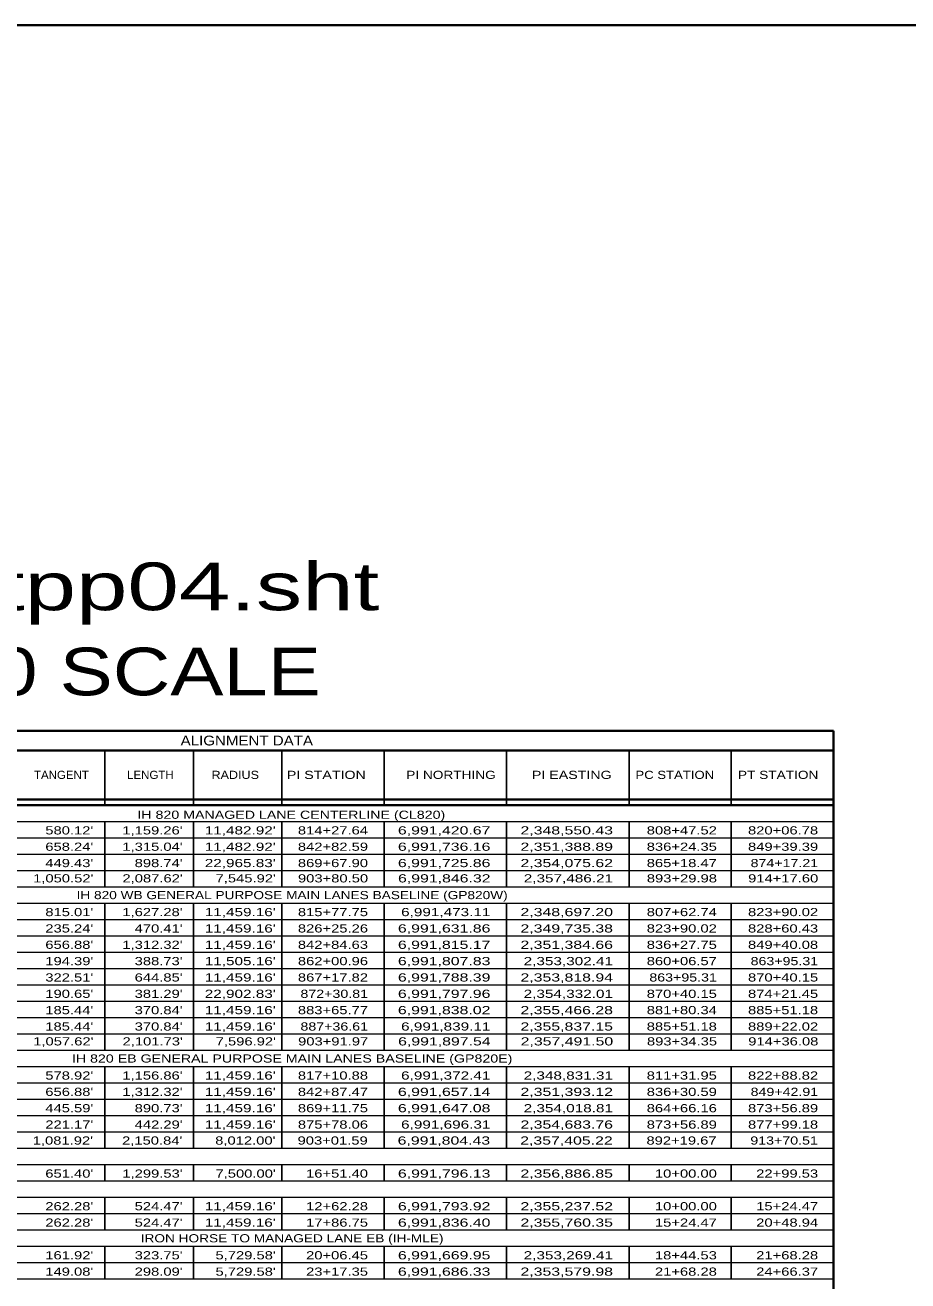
# Model space of a CAD drawing. Extents: x 1953053 to 1967065, y 7363860 to 7371201.
# Drawn here: x 1960493 to 1961790, y 7369357 to 7371201 of the extents above; entities that cross this region are included whole.
import ezdxf
from ezdxf.enums import TextEntityAlignment as Align

# ---------------------------------------------------------------- set-up
doc = ezdxf.new("R2010")
doc.units = 0
doc.header["$LTSCALE"] = 4.8
doc.layers.add('10', color=7, linetype='Continuous')
doc.layers.add('12', color=7, linetype='Continuous', lineweight=25)
doc.layers.add('62', color=7, linetype='Continuous', lineweight=35)

msp = doc.modelspace()

# ---------------------------------------------------------------- linework, layer by layer
at = {"layer": '12', "lineweight": 35}
for p, q in [((1961680.213, 7370164.879), (1959956.881, 7370164.879)), ((1961680.213, 7368159.747), (1961680.213, 7370164.879)), ((1959956.881, 7370136.079), (1961680.213, 7370136.079)), ((1961680.213, 7368111.747), (1961680.213, 7370116.879)), ((1959956.881, 7370064.079), (1961680.213, 7370064.079)), ((1959956.881, 7370055.746), (1961680.213, 7370055.746))]:
    msp.add_line(p, q, dxfattribs=at)
at = {"layer": '12'}
for p, q in [((1960610.213, 7370136.079), (1960610.213, 7370055.746)), ((1960740.213, 7370136.079), (1960740.213, 7370055.746)), ((1960870.213, 7370136.079), (1960870.213, 7370055.746)), ((1961020.213, 7370136.079), (1961020.213, 7370055.746)), ((1961200.213, 7370136.079), (1961200.213, 7370055.746)), ((1961380.213, 7370136.079), (1961380.213, 7370055.746)), ((1961530.213, 7370136.079), (1961530.213, 7370055.746)), ((1960610.213, 7370031.746), (1960610.213, 7369935.746)), ((1960740.213, 7370031.746), (1960740.213, 7369935.746)), ((1960870.213, 7370031.746), (1960870.213, 7369935.746)), ((1961020.213, 7370031.746), (1961020.213, 7369935.746)), ((1961200.213, 7370031.746), (1961200.213, 7369935.746)), ((1961380.213, 7370031.746), (1961380.213, 7369935.746)), ((1961530.213, 7370031.746), (1961530.213, 7369935.746)), ((1960610.213, 7369911.746), (1960610.213, 7369695.746)), ((1960740.213, 7369911.746), (1960740.213, 7369695.746)), ((1960870.213, 7369911.746), (1960870.213, 7369695.746)), ((1961020.213, 7369911.746), (1961020.213, 7369695.746)), ((1961200.213, 7369911.746), (1961200.213, 7369695.746)), ((1961380.213, 7369911.746), (1961380.213, 7369695.746)), ((1961530.213, 7369911.746), (1961530.213, 7369695.746)), ((1960610.213, 7369671.746), (1960610.213, 7369551.746)), ((1960740.213, 7369671.746), (1960740.213, 7369551.746)), ((1960870.213, 7369671.746), (1960870.213, 7369551.746)), ((1961020.213, 7369671.746), (1961020.213, 7369551.746)), ((1961200.213, 7369671.746), (1961200.213, 7369551.746)), ((1961380.213, 7369671.746), (1961380.213, 7369551.746)), ((1961530.213, 7369671.746), (1961530.213, 7369551.746)), ((1960610.213, 7369527.746), (1960610.213, 7369503.746)), ((1960740.213, 7369527.746), (1960740.213, 7369503.746)), ((1960870.213, 7369527.746), (1960870.213, 7369503.746)), ((1961020.213, 7369527.746), (1961020.213, 7369503.746)), ((1961200.213, 7369527.746), (1961200.213, 7369503.746)), ((1961380.213, 7369527.746), (1961380.213, 7369503.746)), ((1961530.213, 7369527.746), (1961530.213, 7369503.746)), ((1960610.213, 7369479.746), (1960610.213, 7369431.746)), ((1960740.213, 7369479.746), (1960740.213, 7369431.746)), ((1960870.213, 7369479.746), (1960870.213, 7369431.746)), ((1961020.213, 7369479.746), (1961020.213, 7369431.746)), ((1961200.213, 7369479.746), (1961200.213, 7369431.746)), ((1961380.213, 7369479.746), (1961380.213, 7369431.746)), ((1961530.213, 7369479.746), (1961530.213, 7369431.746)), ((1960610.213, 7369407.746), (1960610.213, 7369359.746)), ((1960740.213, 7369407.746), (1960740.213, 7369359.746)), ((1960870.213, 7369407.746), (1960870.213, 7369359.746)), ((1961020.213, 7369407.746), (1961020.213, 7369359.746)), ((1961200.213, 7369407.746), (1961200.213, 7369359.746)), ((1961380.213, 7369407.746), (1961380.213, 7369359.746)), ((1961530.213, 7369407.746), (1961530.213, 7369359.746))]:
    msp.add_line(p, q, dxfattribs=at)
at = {"layer": '12', "lineweight": 13}
for p, q in [((1959956.881, 7370007.746), (1961680.213, 7370007.746)), ((1959956.881, 7369983.746), (1961680.213, 7369983.746)), ((1959956.881, 7369959.746), (1961680.213, 7369959.746)), ((1959956.881, 7369935.746), (1961680.213, 7369935.746)), ((1959956.881, 7369911.746), (1961680.213, 7369911.746)), ((1959956.881, 7369887.746), (1961680.213, 7369887.746)), ((1959956.881, 7369863.746), (1961680.213, 7369863.746)), ((1959956.881, 7369839.746), (1961680.213, 7369839.746)), ((1959956.881, 7369815.746), (1961680.213, 7369815.746)), ((1959956.881, 7369791.746), (1961680.213, 7369791.746)), ((1959956.881, 7369767.746), (1961680.213, 7369767.746)), ((1959956.881, 7369743.746), (1961680.213, 7369743.746)), ((1959956.881, 7369719.746), (1961680.213, 7369719.746)), ((1959956.881, 7369695.746), (1961680.213, 7369695.746)), ((1959956.881, 7369647.746), (1961680.213, 7369647.746)), ((1959956.881, 7369623.746), (1961680.213, 7369623.746)), ((1959956.881, 7369599.746), (1961680.213, 7369599.746)), ((1959956.881, 7369575.746), (1961680.213, 7369575.746)), ((1959956.881, 7369551.746), (1961680.213, 7369551.746)), ((1959956.881, 7369527.746), (1961680.213, 7369527.746)), ((1959956.881, 7369503.746), (1961680.213, 7369503.746)), ((1959956.881, 7369479.746), (1961680.213, 7369479.746)), ((1959956.881, 7369455.746), (1961680.213, 7369455.746)), ((1959956.881, 7369431.746), (1961680.213, 7369431.746)), ((1959956.881, 7369407.746), (1961680.213, 7369407.746)), ((1959956.881, 7369383.746), (1961680.213, 7369383.746)), ((1959956.881, 7369359.746), (1961680.213, 7369359.746))]:
    msp.add_line(p, q, dxfattribs=at)
for points in [[(1959956.881, 7370031.746), (1960867.445, 7370031.746), (1961680.213, 7370031.746)], [(1959956.881, 7369671.746), (1961378.496, 7369671.746), (1961680.213, 7369671.746)]]:
    msp.add_lwpolyline(points, dxfattribs=at)
at = {"layer": '62'}
msp.add_lwpolyline([(1953052.784, 7371201.108), (1967065.314, 7371201.108), (1967065.314, 7363859.877), (1953052.784, 7363859.877)], close=True, dxfattribs=at)

# ---------------------------------------------------------------- texts
at = {"layer": '10'}
for s, width, p in [('IH 820 MANAGED LANE CENTERLINE (CL820)', 1.3, (1960884.005, 7370035.509)), ('IH 820 WB GENERAL PURPOSE MAIN LANES BASELINE (GP820W)', 1.25, (1960885.214, 7369917.54)), ('IH 820 EB GENERAL PURPOSE MAIN LANES BASELINE (GP820E)', 1.3, (1960885.214, 7369677.54)), ('IRON HORSE TO MANAGED LANE EB (IH-MLE)', 1.25, (1960885.213, 7369413.54))]:
    msp.add_text(s, height=12, dxfattribs=dict(at, width=width)).set_placement(p, align=Align.CENTER)
for s, width, p in [("580.12'", 1.35, (1960593.14, 7370012.573)), ("1,159.26'", 1.35, (1960724.337, 7370012.573)), ("11,482.92'", 1.4, (1960861.106, 7370012.573)), ('814+27.64', 1.35, (1960996.65, 7370012.573)), ('6,991,420.67', 1.45, (1961176.415, 7370012.573)), ('2,348,550.43', 1.45, (1961356.415, 7370012.573)), ('808+47.52', 1.35, (1961508.993, 7370012.573)), ('820+06.78', 1.35, (1961657.725, 7370012.573)), ("658.24'", 1.35, (1960593.14, 7369988.573)), ("1,315.04'", 1.35, (1960724.337, 7369988.573)), ("11,482.92'", 1.4, (1960861.106, 7369988.573)), ('842+82.59', 1.35, (1960996.65, 7369988.573)), ('6,991,736.16', 1.45, (1961176.415, 7369988.573)), ('2,351,388.89', 1.45, (1961356.415, 7369988.573)), ('836+24.35', 1.35, (1961508.993, 7369988.573)), ('849+39.39', 1.35, (1961657.725, 7369988.573)), ("449.43'", 1.35, (1960593.14, 7369964.573)), ("898.74'", 1.35, (1960724.337, 7369964.573)), ("22,965.83'", 1.4, (1960861.106, 7369964.573)), ('869+67.90', 1.35, (1960996.65, 7369964.573)), ('6,991,725.86', 1.45, (1961176.415, 7369964.573)), ('2,354,075.62', 1.45, (1961356.415, 7369964.573)), ('865+18.47', 1.35, (1961508.993, 7369964.573)), ('874+17.21', 1.3, (1961657.725, 7369964.573)), ("1,050.52'", 1.35, (1960593.294, 7369942.126)), ("2,087.62'", 1.35, (1960724.491, 7369942.126)), ("7,545.92'", 1.35, (1960861.26, 7369942.126)), ('903+80.50', 1.35, (1960996.804, 7369942.126)), ('6,991,846.32', 1.45, (1961176.569, 7369942.126)), ('2,357,486.21', 1.4, (1961356.569, 7369942.126)), ('893+29.98', 1.35, (1961509.147, 7369942.126)), ('914+17.60', 1.35, (1961657.879, 7369942.126)), ("815.01'", 1.35, (1960593.14, 7369892.573)), ("1,627.28'", 1.35, (1960724.337, 7369892.573)), ("11,459.16'", 1.4, (1960861.106, 7369892.573)), ('815+77.75', 1.35, (1960996.65, 7369892.573)), ('6,991,473.11', 1.4, (1961176.415, 7369892.573)), ('2,348,697.20', 1.45, (1961356.415, 7369892.573)), ('807+62.74', 1.35, (1961508.993, 7369892.573)), ('823+90.02', 1.35, (1961657.725, 7369892.573)), ("235.24'", 1.35, (1960593.14, 7369868.573)), ("470.41'", 1.35, (1960724.337, 7369868.573)), ("11,459.16'", 1.4, (1960861.106, 7369868.573)), ('826+25.26', 1.35, (1960996.65, 7369868.573)), ('6,991,631.86', 1.45, (1961176.415, 7369868.573)), ('2,349,735.38', 1.45, (1961356.415, 7369868.573)), ('823+90.02', 1.35, (1961508.993, 7369868.573)), ('828+60.43', 1.35, (1961657.725, 7369868.573)), ("656.88'", 1.35, (1960593.14, 7369844.573)), ("1,312.32'", 1.35, (1960724.337, 7369844.573)), ("11,459.16'", 1.4, (1960861.106, 7369844.573)), ('842+84.63', 1.35, (1960996.65, 7369844.573)), ('6,991,815.17', 1.45, (1961176.415, 7369844.573)), ('2,351,384.66', 1.45, (1961356.415, 7369844.573)), ('836+27.75', 1.35, (1961508.993, 7369844.573)), ('849+40.08', 1.35, (1961657.725, 7369844.573)), ("194.39'", 1.35, (1960593.14, 7369820.573)), ("388.73'", 1.35, (1960724.337, 7369820.573)), ("11,505.16'", 1.4, (1960861.106, 7369820.573)), ('862+00.96', 1.35, (1960996.65, 7369820.573)), ('6,991,807.83', 1.45, (1961176.415, 7369820.573)), ('2,353,302.41', 1.4, (1961356.415, 7369820.573)), ('860+06.57', 1.35, (1961508.993, 7369820.573)), ('863+95.31', 1.3, (1961657.725, 7369820.573)), ("322.51'", 1.35, (1960593.14, 7369796.573)), ("644.85'", 1.35, (1960724.337, 7369796.573)), ("11,459.16'", 1.4, (1960861.106, 7369796.573)), ('867+17.82', 1.35, (1960996.65, 7369796.573)), ('6,991,788.39', 1.45, (1961176.415, 7369796.573)), ('2,353,818.94', 1.45, (1961356.415, 7369796.573)), ('863+95.31', 1.3, (1961508.993, 7369796.573)), ('870+40.15', 1.35, (1961657.725, 7369796.573)), ("190.65'", 1.35, (1960593.14, 7369772.573)), ("381.29'", 1.35, (1960724.337, 7369772.573)), ("22,902.83'", 1.4, (1960861.106, 7369772.573)), ('872+30.81', 1.3, (1960996.65, 7369772.573)), ('6,991,797.96', 1.45, (1961176.415, 7369772.573)), ('2,354,332.01', 1.4, (1961356.415, 7369772.573)), ('870+40.15', 1.35, (1961508.993, 7369772.573)), ('874+21.45', 1.35, (1961657.725, 7369772.573)), ("185.44'", 1.35, (1960593.14, 7369748.573)), ("370.84'", 1.35, (1960724.337, 7369748.573)), ("11,459.16'", 1.4, (1960861.106, 7369748.573)), ('883+65.77', 1.35, (1960996.65, 7369748.573)), ('6,991,838.02', 1.45, (1961176.415, 7369748.573)), ('2,355,466.28', 1.45, (1961356.415, 7369748.573)), ('881+80.34', 1.35, (1961508.993, 7369748.573)), ('885+51.18', 1.35, (1961657.725, 7369748.573)), ("185.44'", 1.35, (1960593.14, 7369724.573)), ("370.84'", 1.35, (1960724.337, 7369724.573)), ("11,459.16'", 1.4, (1960861.106, 7369724.573)), ('887+36.61', 1.3, (1960996.65, 7369724.573)), ('6,991,839.11', 1.4, (1961176.415, 7369724.573)), ('2,355,837.15', 1.45, (1961356.415, 7369724.573)), ('885+51.18', 1.35, (1961508.993, 7369724.573)), ('889+22.02', 1.35, (1961657.725, 7369724.573)), ("1,057.62'", 1.35, (1960593.439, 7369702.722)), ("2,101.73'", 1.35, (1960724.636, 7369702.722)), ("7,596.92'", 1.35, (1960861.405, 7369702.722)), ('903+91.97', 1.35, (1960996.949, 7369702.722)), ('6,991,897.54', 1.45, (1961176.714, 7369702.722)), ('2,357,491.50', 1.45, (1961356.714, 7369702.722)), ('893+34.35', 1.35, (1961509.292, 7369702.722)), ('914+36.08', 1.35, (1961658.024, 7369702.722)), ("578.92'", 1.35, (1960593.14, 7369652.573)), ("1,156.86'", 1.35, (1960724.337, 7369652.573)), ("11,459.16'", 1.4, (1960861.106, 7369652.573)), ('817+10.88', 1.35, (1960996.65, 7369652.573)), ('6,991,372.41', 1.4, (1961176.415, 7369652.573)), ('2,348,831.31', 1.4, (1961356.415, 7369652.573)), ('811+31.95', 1.35, (1961508.993, 7369652.573)), ('822+88.82', 1.35, (1961657.725, 7369652.573)), ("656.88'", 1.35, (1960593.14, 7369628.573)), ("1,312.32'", 1.35, (1960724.337, 7369628.573)), ("11,459.16'", 1.4, (1960861.106, 7369628.573)), ('842+87.47', 1.35, (1960996.65, 7369628.573)), ('6,991,657.14', 1.45, (1961176.415, 7369628.573)), ('2,351,393.12', 1.45, (1961356.415, 7369628.573)), ('836+30.59', 1.35, (1961508.993, 7369628.573)), ('849+42.91', 1.3, (1961657.725, 7369628.573)), ("445.59'", 1.35, (1960593.14, 7369604.573)), ("890.73'", 1.35, (1960724.337, 7369604.573)), ("11,459.16'", 1.4, (1960861.106, 7369604.573)), ('869+11.75', 1.35, (1960996.65, 7369604.573)), ('6,991,647.08', 1.45, (1961176.415, 7369604.573)), ('2,354,018.81', 1.4, (1961356.415, 7369604.573)), ('864+66.16', 1.35, (1961508.993, 7369604.573)), ('873+56.89', 1.35, (1961657.725, 7369604.573)), ("221.17'", 1.35, (1960593.14, 7369580.573)), ("442.29'", 1.35, (1960724.337, 7369580.573)), ("11,459.16'", 1.4, (1960861.106, 7369580.573)), ('875+78.06', 1.35, (1960996.65, 7369580.573)), ('6,991,696.31', 1.4, (1961176.415, 7369580.573)), ('2,354,683.76', 1.45, (1961356.415, 7369580.573)), ('873+56.89', 1.35, (1961508.993, 7369580.573)), ('877+99.18', 1.35, (1961657.725, 7369580.573)), ("1,081.92'", 1.35, (1960592.726, 7369557.11)), ("2,150.84'", 1.35, (1960723.923, 7369557.11)), ("8,012.00'", 1.35, (1960860.692, 7369557.11)), ('903+01.59', 1.35, (1960996.236, 7369557.11)), ('6,991,804.43', 1.45, (1961176.001, 7369557.11)), ('2,357,405.22', 1.45, (1961356.001, 7369557.11)), ('892+19.67', 1.35, (1961508.579, 7369557.11)), ('913+70.51', 1.3, (1961657.311, 7369557.11)), ("651.40'", 1.35, (1960593.14, 7369508.573)), ("1,299.53'", 1.35, (1960724.337, 7369508.573)), ("7,500.00'", 1.35, (1960861.106, 7369508.573)), ('16+51.40', 1.35, (1960996.65, 7369508.573)), ('6,991,796.13', 1.45, (1961176.415, 7369508.573)), ('2,356,886.85', 1.45, (1961356.415, 7369508.573)), ('10+00.00', 1.35, (1961508.993, 7369508.573)), ('22+99.53', 1.35, (1961657.725, 7369508.573)), ("262.28'", 1.35, (1960593.14, 7369460.573)), ("524.47'", 1.35, (1960724.337, 7369460.573)), ("11,459.16'", 1.4, (1960861.106, 7369460.573)), ('12+62.28', 1.35, (1960996.65, 7369460.573)), ('6,991,793.92', 1.45, (1961176.415, 7369460.573)), ('2,355,237.52', 1.45, (1961356.415, 7369460.573)), ('10+00.00', 1.35, (1961508.993, 7369460.573)), ('15+24.47', 1.35, (1961657.725, 7369460.573)), ("262.28'", 1.35, (1960593.14, 7369436.573)), ("524.47'", 1.35, (1960724.337, 7369436.573)), ("11,459.16'", 1.4, (1960861.106, 7369436.573)), ('17+86.75', 1.35, (1960996.65, 7369436.573)), ('6,991,836.40', 1.45, (1961176.415, 7369436.573)), ('2,355,760.35', 1.45, (1961356.415, 7369436.573)), ('15+24.47', 1.35, (1961508.993, 7369436.573)), ('20+48.94', 1.35, (1961657.725, 7369436.573)), ("161.92'", 1.35, (1960593.14, 7369388.573)), ("323.75'", 1.35, (1960724.337, 7369388.573)), ("5,729.58'", 1.35, (1960861.106, 7369388.573)), ('20+06.45', 1.35, (1960996.65, 7369388.573)), ('6,991,669.95', 1.45, (1961176.415, 7369388.573)), ('2,353,269.41', 1.4, (1961356.415, 7369388.573)), ('18+44.53', 1.35, (1961508.993, 7369388.573)), ('21+68.28', 1.35, (1961657.725, 7369388.573)), ("149.08'", 1.35, (1960593.14, 7369364.573)), ("298.09'", 1.35, (1960724.337, 7369364.573)), ("5,729.58'", 1.35, (1960861.106, 7369364.573)), ('23+17.35', 1.35, (1960996.65, 7369364.573)), ('6,991,686.33', 1.45, (1961176.415, 7369364.573)), ('2,353,579.98', 1.45, (1961356.415, 7369364.573)), ('21+68.28', 1.35, (1961508.993, 7369364.573)), ('24+66.37', 1.35, (1961657.725, 7369364.573))]:
    msp.add_text(s, height=12, dxfattribs=dict(at, width=width)).set_placement(p, align=Align.RIGHT)
at = {"layer": '12'}
for s, height, width, p in [('ALIGNMENT DATA', 14.4, 1.15, (1960818.654, 7370143.278)), ('TANGENT', 12, 1.05, (1960546.401, 7370094.078)), ('LENGTH', 12, 1.05, (1960677.036, 7370094.078)), ('RADIUS', 12, 1.15, (1960801.646, 7370094.078)), ('PI STATION', 12, 1.3, (1960935.45, 7370094.078)), ('PI NORTHING', 12, 1.25, (1961118.525, 7370094.078)), ('PI EASTING', 12, 1.3, (1961295.917, 7370094.078)), ('PC STATION', 12, 1.2, (1961447.222, 7370094.078)), ('PT STATION', 12, 1.25, (1961598.993, 7370094.078))]:
    msp.add_text(s, height=height, dxfattribs=dict(at, width=width)).set_placement(p, align=Align.CENTER)
at = {"layer": '62'}
for s, width, p in [('820tpp04.sht', 1.45, (1960620.637, 7370341.878)), ('200 SCALE', 1.25, (1960621.745, 7370216.878))]:
    msp.add_text(s, height=70, dxfattribs=dict(at, width=width)).set_placement(p, align=Align.CENTER)

doc.saveas('drawing.dxf')
